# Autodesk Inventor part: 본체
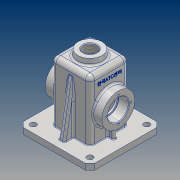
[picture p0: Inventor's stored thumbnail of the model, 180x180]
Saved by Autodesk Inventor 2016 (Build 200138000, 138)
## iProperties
Created: 2018-10
Part Number: 본체
Material: 알루미늄 6061
Document SubType Name: Modeling
Designer: user
Density: 2.7 g/cm^3
Appearance: 알루미늄 - 평지
Mass: 794.227 g
Surface Area: 899.5 cm^2
Volume: 294.158 cm^3
Author: user
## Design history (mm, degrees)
sketch "스케치1"
  geometry: L1 (-60, 60)-(60, 60); L2 (60, 60)-(60, -60); L3 (60, -60)-(-60, -60); L4 (-60, -60)-(-60, 60); L5 (-60, 60)-(60, -60); L6 (60, 60)-(-60, -60); 1 further point
  constraints: 12 end point, 2 midpoint, 2 parallel, 1 horizontal, 1 perpendicular
  dimensions: "d0" = 120 distance of L2.end L3.end; "d1" = 120 distance of L1.end L2.end
extrude "돌출1" new body sketch "스케치1" distance "d2" = 10; taper "d3" = 0 deg
sketch "스케치2"
  geometry: L1 (60, 60)-(-60, 60) reference; L2 (-47.5, 47.5)-(47.5, 47.5); L3 (47.5, 47.5)-(47.5, -47.5); L4 (47.5, -47.5)-(-47.5, -47.5); L5 (-47.5, -47.5)-(-47.5, 47.5); L6 (-47.5, 47.5)-(47.5, -47.5); L7 (47.5, 47.5)-(-47.5, -47.5); C1 r 5 at (-47.5, 47.5); C2 r 5 at (-47.5, -47.5); C3 r 5 at (47.5, 47.5); C4 r 5 at (47.5, -47.5); 1 further point
  constraints: 12 end point, 4 centre point, 4 coincident, 2 midpoint, 2 parallel, 1 horizontal, 1 perpendicular
  dimensions: "d10" = 95 distance of L3.end L4.end; "d11" = 95 distance of L2.end L3.end; "d12" = 10 diameter of C1; "d13" = 10 diameter of C3; "d14" = 10 diameter of C4; "d15" = 10 diameter of C2
extrude "돌출2" cut sketch "스케치2" distance "d16" = 10; taper "d17" = 0 deg
sketch "스케치3"
  geometry: L1 (-32.5, 32.5)-(32.5, 32.5); L2 (32.5, 32.5)-(32.5, -32.5); L3 (32.5, -32.5)-(-32.5, -32.5); L4 (-32.5, -32.5)-(-32.5, 32.5); L5 (-32.5, 32.5)-(32.5, -32.5); L6 (32.5, 32.5)-(-32.5, -32.5); 1 further point
  constraints: 12 end point, 2 midpoint, 2 parallel, 1 horizontal, 1 perpendicular
  dimensions: "d18" = 65 distance of L1.start L1.end; "d19" = 65 distance of L1.end L2.end
extrude "돌출3" join sketch "스케치3" distance "d20" = 100; taper "d21" = 0 deg
fillet "모깎기1" dims "d22" = 8
fillet "모깎기2" dims "d23" = 8
chamfer "모따기1" distance "d24" = 8; stored, may be unused: second distance "d25" = 2, angle "d26" = 45 deg
feature "쉘1" dims "d27" = 10, "d28" = 5
node "작업 평면1"
sketch "스케치4"
  geometry: C1 r 20 at (0, 0); 1 further point
  constraints: 1 centre point, 1 coincident
  dimensions: "d30" = 40 diameter of C1
extrude "돌출4" join sketch "스케치4" stored distance "d31" = 100; taper "d32" = 7 deg
sketch "스케치5"
  geometry: L1 (102, 49)-(102, 0) reference; C1 r 27.5 at (47, 24.5); 2 further points
  constraints: 1 centre point, 1 horizontal alignment, 1 midpoint
  dimensions: "d33" = 55 diameter of C1; "d34" = 55 distance of point (102, 24.5) C1.centre
extrude "돌출5" join sketch "스케치5" distance "d35" = 20; taper "d36" = 0 deg
hole "구멍1" diameter "d39" = 30; stored, may be unused: countersink angle "d43" = 90 deg, drill point angle "d45" = 118 deg; dims "d37" = 10, "d38" = 10, "d40" = 6, "d41" = 35, "d42" = 17, "d44" = 8
sketch "스케치6"
  geometry: C1 r 20 at (0, 0) reference; 1 further point
  constraints: 1 coincident
hole "구멍2" sketch "스케치6" at (0, 0) diameter "d46" = 22.835; stored, may be unused: countersink angle "d50" = 90 deg, drill point angle "d52" = 118 deg; dims "d47" = 50, "d48" = 35, "d49" = 17, "d51" = 59.3
sketch "스케치7"
  geometry: C1 r 17.5 at (0, 0) reference; 2 further points
  constraints: 1 horizontal alignment
  dimensions: "d53" = 21 distance of C1.centre point (21, 0)
hole "구멍3" sketch "스케치7" at (21, 0) diameter "d54" = 3.242; stored, may be unused: countersink angle "d58" = 90 deg, drill point angle "d60" = 118 deg; dims "d55" = 8, "d56" = 35, "d57" = 17, "d59" = 10
sketch "스케치8"
  geometry: L1 (60, 10)-(52, 10) reference; L2 (48, 10)-(32.5, 97.905); L3 (32.5, 10)-(32.5, 102) reference; L4 (60, 0)-(60, 10) reference; L5 (32.5, 10)-(24.5, 10) reference; L6 (48, 10)-(32.5, 10); 1 further point
  constraints: 4 end point, 2 point on line, 1 horizontal
  dimensions: "d64" = 10 deg angle of L4 L2; "d65" = 12 distance from line of L4 L2.start
extrude "돌출6" join sketch "스케치8" stored distance "d66" = 10; taper "d67" = 0 deg
sketch "스케치9"
  geometry: L1 (42.5, 30.354)-(42.5, 10); L2 (42.5, 10)-(52.5, 10) reference; L3 (-52, 10)-(52, 10) reference; L4 (27.5, 0)-(27.5, 102) reference; L5 (32.5, 42.51)-(32.5, 27.5) reference; L6 (42.5, 30.354)-(32.5, 30.354); L7 (42.5, 10)-(32.5, 10); L8 (32.5, 10)-(32.5, 42.51) reference; L9 (32.5, 30.354)-(32.5, 10); 1 further point
  constraints: 8 end point, 2 collinear, 2 point on line, 1 perpendicular, 1 vertical
  dimensions: "d68" = 15 distance between parallel lines of L4 L1; "d73" = 20.35361 distance between parallel lines of L3 L6
extrude "돌출7" join sketch "스케치9" stored distance "d69" = 6; taper "d70" = 0 deg
fillet "모깎기3" dims "d71" = 3
fillet "모깎기4" dims "d72" = 3
fillet "모깎기5" dims "d74" = 3
fillet "모깎기6" dims "d75" = 3
fillet "모깎기7" dims "d76" = 1
chamfer "모따기2" distance "d77" = 1; stored, may be unused: second distance "d78" = 2, angle "d79" = 45 deg
fillet "모깎기8" dims "d80" = 0.3
sketch "스케치10"
  geometry: L1 (-18, 4.5)-(-18, 44.5) reference; A1 r 30.5 centre (47, 24.5) between (28.834, 49) and (28.834, 0) reference; 2 further points
  constraints: 1 horizontal alignment, 1 other
  dimensions: "d81" = 26 distance from line of L1 point (8, 24.5)
feature "엠보싱1" sketch "스케치10" dims "d16" = 10, "d82" = 0.5, "d83" = 0
node "솔리드1"
mirror "대칭1"
pattern_circular "원형 패턴1" dims angle "d62" = 360 deg
mirror "대칭2"
mirror "대칭3"
mirror "대칭4"
